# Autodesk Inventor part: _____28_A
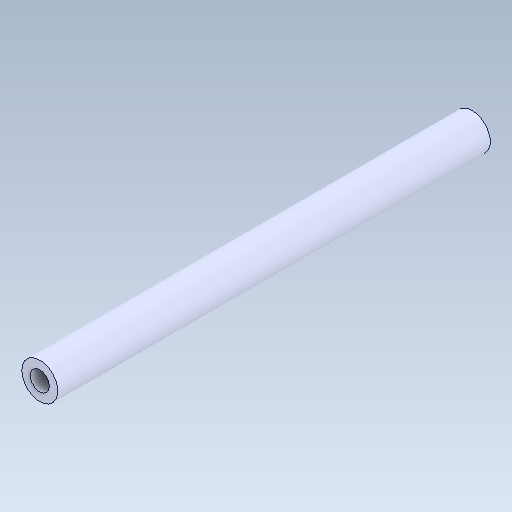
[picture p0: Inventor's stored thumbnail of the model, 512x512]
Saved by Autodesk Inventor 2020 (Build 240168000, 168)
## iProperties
Created: 2017-09
Part Number: _____28_A
Material: Générique
Document SubType Name: Modeling
Designer: bruno
Density: 1 g/cm^3
Appearance: Par défaut
Author: bruno
Sending System: SolidWorks 2016
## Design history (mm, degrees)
feature "Importée1"
node "Solide1"
